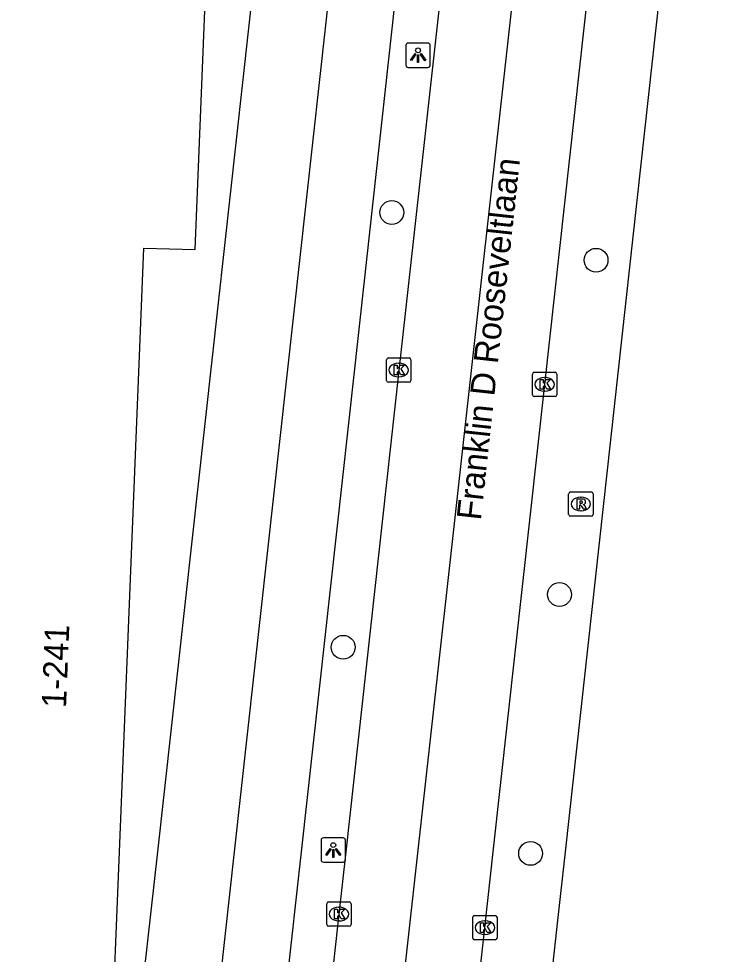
# Model space of a CAD drawing. Extents: x 160891 to 161384, y 386490 to 386907.
# Drawn here: x 161353.39 to 161382.71, y 386745.8 to 386784.23 of the extents above; entities that cross this region are included whole.
import ezdxf

# ---------------------------------------------------------------- set-up
doc = ezdxf.new("R2010")
doc.units = 0
for name, color, linetype in [('IMGEO_Boom', 7, 'Continuous'), ('IMGEO_Fietspad_gesloten', 7, 'Continuous'), ('IMGEO_Kolk', 7, 'Continuous'), ('IMGEO_Lichtpunt', 7, 'Continuous'), ('IMGEO_Openbare_ruimte_label', 7, 'Continuous'), ('IMGEO_Pand', 7, 'Continuous'), ('IMGEO_Pand_nummerreeks', 7, 'Continuous'), ('IMGEO_Rijbaan_lokaal_gesloten', 7, 'Continuous'), ('IMGEO_Rioolput', 7, 'Continuous'), ('IMGEO_Voetpad_open', 7, 'Continuous')]:
    doc.layers.add(name, color=color, linetype=linetype)

msp = doc.modelspace()

# ---------------------------------------------------------------- linework, layer by layer
at = {"layer": 'IMGEO_Boom'}
for centre in [(161368.715, 386776.272), (161377.108, 386774.309), (161375.606, 386760.578), (161366.718, 386758.41), (161374.42, 386749.942)]:
    msp.add_circle(centre, 0.489, dxfattribs=at)
at = {"layer": 'IMGEO_Fietspad_gesloten'}
for points in [[(161370.409, 386823.612), (161369.942, 386819.493), (161368.96, 386810.871), (161362.241, 386750), (161360.898, 386737.834), (161359.269, 386727.112)], [(161361.755, 386725.593), (161362.922, 386732.791), (161363.779, 386738.891), (161365.004, 386750), (161367.179, 386769.719), (161371.658, 386810.524), (161372.043, 386813.873)]]:
    msp.add_lwpolyline(points, dxfattribs=at)
at = {"layer": 'IMGEO_Kolk'}
for p, q in [((161368.574, 386770.299), (161369.426, 386770.299)), ((161368.499, 386769.373), (161368.499, 386770.225)), ((161368.987, 386770.079), (161369.012, 386770.079)), ((161369.5, 386770.225), (161369.5, 386769.373)), ((161369.01, 386769.519), (161368.985, 386769.519)), ((161374.497, 386768.783), (161374.497, 386769.635)), ((161374.572, 386769.709), (161375.424, 386769.709)), ((161375.498, 386769.635), (161375.498, 386768.783)), ((161369.426, 386769.299), (161368.574, 386769.299)), ((161374.985, 386769.489), (161375.01, 386769.489)), ((161375.008, 386768.929), (161374.983, 386768.929)), ((161375.424, 386768.709), (161374.572, 386768.709)), ((161366.044, 386747.022), (161366.044, 386747.874)), ((161366.119, 386747.948), (161366.971, 386747.948)), ((161366.532, 386747.728), (161366.557, 386747.728)), ((161367.045, 386747.874), (161367.045, 386747.022)), ((161372.043, 386746.463), (161372.043, 386747.315)), ((161372.118, 386747.389), (161372.97, 386747.389)), ((161373.044, 386747.315), (161373.044, 386746.463)), ((161366.971, 386746.948), (161366.119, 386746.948)), ((161366.555, 386747.168), (161366.53, 386747.168)), ((161372.531, 386747.169), (161372.556, 386747.169)), ((161372.554, 386746.609), (161372.529, 386746.609)), ((161372.97, 386746.389), (161372.118, 386746.389))]:
    msp.add_line(p, q, dxfattribs=at)
for points in [[(161368.574, 386770.299), (161369.426, 386770.299)], [(161368.499, 386769.373), (161368.499, 386770.225)], [(161368.82, 386769.999), (161368.943, 386769.999), (161368.943, 386769.848), (161369.073, 386769.999), (161369.237, 386769.999), (161369.091, 386769.848), (161369.244, 386769.599), (161369.092, 386769.599), (161369.007, 386769.763), (161368.943, 386769.696), (161368.943, 386769.599), (161368.82, 386769.599), (161368.82, 386769.999)], [(161369.5, 386770.225), (161369.5, 386769.373)], [(161374.497, 386768.783), (161374.497, 386769.635)], [(161374.572, 386769.709), (161375.424, 386769.709)], [(161375.498, 386769.635), (161375.498, 386768.783)], [(161369.426, 386769.299), (161368.574, 386769.299)], [(161374.818, 386769.409), (161374.941, 386769.409), (161374.941, 386769.258), (161375.071, 386769.409), (161375.235, 386769.409), (161375.089, 386769.258), (161375.242, 386769.009), (161375.09, 386769.009), (161375.005, 386769.173), (161374.941, 386769.106), (161374.941, 386769.009), (161374.818, 386769.009), (161374.818, 386769.409)], [(161375.424, 386768.709), (161374.572, 386768.709)], [(161366.044, 386747.022), (161366.044, 386747.874)], [(161366.119, 386747.948), (161366.971, 386747.948)], [(161366.365, 386747.648), (161366.488, 386747.648), (161366.488, 386747.497), (161366.618, 386747.648), (161366.782, 386747.648), (161366.636, 386747.497), (161366.789, 386747.248), (161366.637, 386747.248), (161366.552, 386747.412), (161366.488, 386747.345), (161366.488, 386747.248), (161366.365, 386747.248), (161366.365, 386747.648)], [(161367.045, 386747.874), (161367.045, 386747.022)], [(161372.043, 386746.463), (161372.043, 386747.315)], [(161372.118, 386747.389), (161372.97, 386747.389)], [(161373.044, 386747.315), (161373.044, 386746.463)], [(161366.971, 386746.948), (161366.119, 386746.948)], [(161372.364, 386747.089), (161372.487, 386747.089), (161372.487, 386746.938), (161372.617, 386747.089), (161372.781, 386747.089), (161372.635, 386746.938), (161372.788, 386746.689), (161372.636, 386746.689), (161372.551, 386746.853), (161372.487, 386746.786), (161372.487, 386746.689), (161372.364, 386746.689), (161372.364, 386747.089)], [(161372.97, 386746.389), (161372.118, 386746.389)]]:
    msp.add_lwpolyline(points, dxfattribs=at)
for centre, start, end in [((161368.576, 386770.223), 91.552, 178.448), ((161368.576, 386770.223), 91.552, 178.448), ((161369.424, 386770.223), 1.552, 88.448), ((161369.424, 386770.223), 1.552, 88.448), ((161374.574, 386769.633), 91.552, 178.448), ((161374.574, 386769.633), 91.552, 178.448), ((161375.422, 386769.633), 1.552, 88.448), ((161375.422, 386769.633), 1.552, 88.448), ((161368.576, 386769.375), 181.552, 268.448), ((161368.576, 386769.375), 181.552, 268.448), ((161369.424, 386769.375), 271.552, 358.448), ((161369.424, 386769.375), 271.552, 358.448), ((161374.574, 386768.785), 181.552, 268.448), ((161374.574, 386768.785), 181.552, 268.448), ((161375.422, 386768.785), 271.552, 358.448), ((161375.422, 386768.785), 271.552, 358.448), ((161366.121, 386747.872), 91.552, 178.448), ((161366.121, 386747.872), 91.552, 178.448), ((161366.969, 386747.872), 1.552, 88.448), ((161366.969, 386747.872), 1.552, 88.448), ((161372.12, 386747.313), 91.552, 178.448), ((161372.12, 386747.313), 91.552, 178.448), ((161372.968, 386747.313), 1.552, 88.448), ((161372.968, 386747.313), 1.552, 88.448), ((161366.121, 386747.024), 181.552, 268.448), ((161366.121, 386747.024), 181.552, 268.448), ((161366.969, 386747.024), 271.552, 358.448), ((161366.969, 386747.024), 271.552, 358.448), ((161372.12, 386746.465), 181.552, 268.448), ((161372.12, 386746.465), 181.552, 268.448), ((161372.968, 386746.465), 271.552, 358.448), ((161372.968, 386746.465), 271.552, 358.448)]:
    msp.add_arc(centre, 0.0765, start, end, dxfattribs=at)
for centre, major_axis, ratio, start_param, end_param in [((161368.986, 386769.799), (-0.387, 0.002), 0.722429, 4.712389, 7.853982), ((161369.011, 386769.799), (-0.39, 0.002), 0.717154, 1.570796, 4.712389), ((161374.984, 386769.209), (-0.387, 0.002), 0.722429, 4.712389, 7.853982), ((161375.009, 386769.209), (-0.39, 0.002), 0.717154, 1.570796, 4.712389), ((161366.531, 386747.448), (-0.387, 0.002), 0.722429, 4.712389, 7.853982), ((161366.556, 386747.448), (-0.39, 0.002), 0.717154, 1.570796, 4.712389), ((161372.53, 386746.889), (-0.387, 0.002), 0.722429, 4.712389, 7.853982), ((161372.555, 386746.889), (-0.39, 0.002), 0.717154, 1.570796, 4.712389)]:
    msp.add_ellipse(centre, major_axis=major_axis, ratio=ratio, start_param=start_param, end_param=end_param, dxfattribs=at)
at = {"layer": 'IMGEO_Lichtpunt'}
for p, q in [((161369.297, 386783.135), (161369.297, 386782.328)), ((161369.297, 386783.135), (161369.297, 386782.328)), ((161370.199, 386783.23), (161369.391, 386783.23)), ((161370.199, 386783.23), (161369.391, 386783.23)), ((161370.293, 386782.328), (161370.293, 386783.135)), ((161370.293, 386782.328), (161370.293, 386783.135)), ((161369.391, 386782.234), (161370.199, 386782.234)), ((161369.391, 386782.234), (161370.199, 386782.234)), ((161365.812, 386750.484), (161365.812, 386749.677)), ((161365.812, 386750.484), (161365.812, 386749.677)), ((161366.714, 386750.579), (161365.906, 386750.579)), ((161366.714, 386750.579), (161365.906, 386750.579)), ((161366.808, 386749.677), (161366.808, 386750.484)), ((161366.808, 386749.677), (161366.808, 386750.484)), ((161365.906, 386749.583), (161366.714, 386749.583)), ((161365.906, 386749.583), (161366.714, 386749.583))]:
    msp.add_line(p, q, dxfattribs=at)
for points in [[(161369.671, 386782.799), (161369.71, 386782.771), (161369.522, 386782.509), (161369.484, 386782.536), (161369.671, 386782.799)], [(161369.773, 386782.751), (161369.82, 386782.751), (161369.82, 386782.429), (161369.773, 386782.429), (161369.773, 386782.751)], [(161369.883, 386782.771), (161369.921, 386782.798), (161370.108, 386782.536), (161370.069, 386782.508), (161369.883, 386782.771)], [(161366.186, 386750.148), (161366.225, 386750.12), (161366.037, 386749.858), (161365.999, 386749.885), (161366.186, 386750.148)], [(161366.288, 386750.1), (161366.335, 386750.1), (161366.335, 386749.778), (161366.288, 386749.778), (161366.288, 386750.1)], [(161366.398, 386750.12), (161366.436, 386750.147), (161366.623, 386749.885), (161366.584, 386749.857), (161366.398, 386750.12)]]:
    msp.add_lwpolyline(points, dxfattribs=at)
for centre in [(161369.796, 386782.933), (161366.311, 386750.282)]:
    msp.add_circle(centre, 0.0994, dxfattribs=at)
for centre, start, end in [((161369.391, 386783.135), 90, 180), ((161369.391, 386783.135), 90, 180), ((161370.199, 386783.135), 0, 90), ((161370.199, 386783.135), 0, 90), ((161369.391, 386782.328), 180, 270), ((161369.391, 386782.328), 180, 270), ((161370.199, 386782.328), 270, 0), ((161370.199, 386782.328), 270, 360), ((161365.906, 386750.484), 90, 180), ((161365.906, 386750.484), 90, 180), ((161366.714, 386750.484), 0, 90), ((161366.714, 386750.484), 0, 90), ((161365.906, 386749.677), 180, 270), ((161365.906, 386749.677), 180, 270), ((161366.714, 386749.677), 270, 0), ((161366.714, 386749.677), 270, 360)]:
    msp.add_arc(centre, 0.0946, start, end, dxfattribs=at)
at = {"layer": 'IMGEO_Pand'}
msp.add_lwpolyline([(161354.593, 386725.304), (161355.121, 386738.044), (161353.387, 386738.115), (161353.533, 386741.712), (161357.179, 386741.563), (161357.522, 386750), (161358.531, 386774.8), (161360.635, 386774.751), (161362.7, 386825.861)], dxfattribs=at)
at = {"layer": 'IMGEO_Rijbaan_lokaal_gesloten'}
for points in [[(161373.931, 386813.306), (161373.847, 386812.791), (161373.654, 386811.717), (161373.505, 386810.507), (161371.264, 386790.142), (161368.999, 386769.786), (161366.826, 386750), (161366.545, 386747.443), (161364.289, 386727.081), (161364.11, 386725.435), (161364.089, 386725.334)], [(161376.784, 386813.011), (161368.323, 386736.898), (161366.259, 386718.291)], [(161370.136, 386725.225), (161372.544, 386746.889), (161372.886, 386750), (161374.998, 386769.209), (161377.255, 386789.585), (161379.518, 386809.955), (161379.812, 386812.698)], [(161382.706, 386812.365), (161380.179, 386789.468), (161375.835, 386750), (161375.512, 386747.068), (161374.749, 386740.065), (161374.587, 386736.651), (161374.104, 386730.63), (161373.249, 386724.98)]]:
    msp.add_lwpolyline(points, dxfattribs=at)
at = {"layer": 'IMGEO_Rioolput'}
for p, q in [((161375.983, 386763.867), (161375.983, 386764.719)), ((161376.058, 386764.793), (161376.91, 386764.793)), ((161376.471, 386764.573), (161376.496, 386764.573)), ((161376.984, 386764.719), (161376.984, 386763.867)), ((161376.91, 386763.793), (161376.058, 386763.793)), ((161376.494, 386764.013), (161376.469, 386764.013))]:
    msp.add_line(p, q, dxfattribs=at)
for points in [[(161375.983, 386763.867), (161375.983, 386764.719)], [(161376.058, 386764.793), (161376.91, 386764.793)], [(161376.984, 386764.719), (161376.984, 386763.867)], [(161376.572, 386764.491), (161376.32, 386764.493), (161376.32, 386764.093)], [(161376.32, 386764.093), (161376.444, 386764.093), (161376.444, 386764.255), (161376.455, 386764.255)], [(161376.498, 386764.412), (161376.444, 386764.412), (161376.444, 386764.331)], [(161376.444, 386764.331), (161376.496, 386764.331)], [(161376.502, 386764.226), (161376.573, 386764.093), (161376.713, 386764.093), (161376.648, 386764.219)], [(161376.91, 386763.793), (161376.058, 386763.793)]]:
    msp.add_lwpolyline(points, dxfattribs=at)
for centre, radius, start, end in [((161376.06, 386764.717), 0.0765, 91.552, 178.448), ((161376.06, 386764.717), 0.0765, 91.552, 178.448), ((161376.908, 386764.717), 0.0765, 1.552, 88.448), ((161376.908, 386764.717), 0.0765, 1.552, 88.448), ((161376.454, 386764.202), 0.0533, 26.0293, 88.6989), ((161376.48, 386764.52), 0.19, 274.7715, 282.9687), ((161376.504, 386764.316), 0.0964, 77.0061, 93.1865), ((161376.518, 386764.373), 0.0378, 276.6634, 79.6772), ((161376.571, 386764.381), 0.109, 350.3612, 89.416), ((161376.569, 386764.381), 0.112, 277.5842, 350.9817), ((161376.553, 386764.166), 0.108, 29.5134, 73.7905), ((161376.06, 386763.869), 0.0765, 181.552, 268.448), ((161376.06, 386763.869), 0.0765, 181.552, 268.448), ((161376.908, 386763.869), 0.0765, 271.552, 358.448), ((161376.908, 386763.869), 0.0765, 271.552, 358.448)]:
    msp.add_arc(centre, radius, start, end, dxfattribs=at)
for centre, major_axis, ratio, start_param, end_param in [((161376.47, 386764.293), (-0.387, 0.002), 0.722429, 4.712389, 7.853982), ((161376.495, 386764.293), (-0.39, 0.002), 0.717154, 1.570796, 4.712389)]:
    msp.add_ellipse(centre, major_axis=major_axis, ratio=ratio, start_param=start_param, end_param=end_param, dxfattribs=at)
at = {"layer": 'IMGEO_Voetpad_open'}
msp.add_lwpolyline([(161367.463, 386825.61), (161365.845, 386811.132), (161361.328, 386770.209), (161359.085, 386750), (161358.409, 386743.907), (161356.352, 386725.232)], dxfattribs=at)

# ---------------------------------------------------------------- texts
at = {"layer": 'IMGEO_Openbare_ruimte_label'}
msp.add_text('Franklin D Rooseveltlaan', height=1, rotation=83.799, dxfattribs=at).set_placement((161372.372, 386763.601))
at = {"layer": 'IMGEO_Pand_nummerreeks'}
msp.add_text('1-241', height=1, rotation=87.6706, dxfattribs=at).set_placement((161355.33, 386755.908))

doc.saveas('drawing.dxf')
